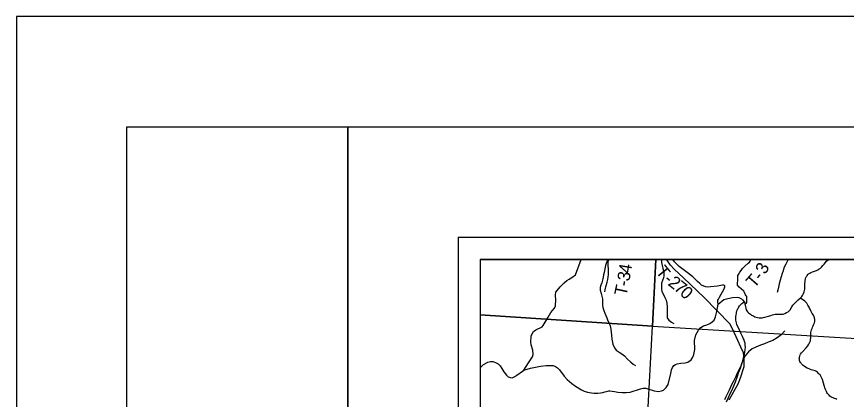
# Model space of a CAD drawing. Extents: x 0 to 34, y 0 to 22.
# Drawn here: x 0 to 3.758, y 20.265 to 22 of the extents above; entities that cross this region are included whole.
import ezdxf

# ---------------------------------------------------------------- set-up
doc = ezdxf.new("R2010")
doc.units = 0
for name, color, linetype in [('GM_X_Corporation', 7, 'Continuous'), ('GM_X_County_Road', 7, 'Continuous'), ('GM_X_Minor_River', 7, 'Continuous'), ('GM_X_Rail_Line', 7, 'Continuous'), ('GM_X_Township_Road', 7, 'Continuous'), ('GM_X_Township_Road_Text', 7, 'Continuous'), ('SH_Border', 7, 'Continuous'), ('SH_Data', 7, 'Continuous')]:
    doc.layers.add(name, color=color, linetype=linetype)

msp = doc.modelspace()

# ---------------------------------------------------------------- linework, layer by layer
at = {"layer": 'GM_X_Corporation'}
for points in [[(3.3441, 14.1), (8.9, 14.1), (8.9, 20.9), (2.1, 20.9), (2.1, 16.1353), (2.1457, 16.065), (2.3447, 15.6926), (2.4297, 15.5215), (2.465, 15.4504), (2.4884, 15.4033), (2.5769, 15.2135), (2.7849, 14.8403), (2.8931, 14.6544), (3.0297, 14.4867), (3.1386, 14.3654), (3.228, 14.2415)], [(2.8947, 20.9), (2.1, 20.9), (2.1, 20.6488), (2.8805, 20.5967)], [(6.9348, 20.9), (2.1, 20.9), (2.1, 19.6396), (2.105, 19.6393), (2.5886, 19.6074), (3.0215, 19.5789), (3.8201, 19.5262), (3.8692, 19.5228), (4.8375, 19.4557), (5.0201, 19.4401), (5.6539, 19.3859), (5.9419, 19.3649), (6.5423, 19.3229), (6.824, 19.3005), (6.835, 19.4037), (6.8961, 20.3303), (6.9032, 20.4198)], [(3.9048, 20.9), (2.8947, 20.9), (2.8805, 20.5967), (3.8795, 20.5363)], [(2.1, 20.6488), (2.1, 19.629), (2.8266, 19.5815), (2.8805, 20.5967)], [(3.8795, 20.5363), (3.8179, 19.5177), (2.8266, 19.5815), (2.8805, 20.5967)]]:
    msp.add_lwpolyline(points, close=True, dxfattribs=at)
at = {"layer": 'GM_X_County_Road'}
msp.add_lwpolyline([(3.7158, 20.265), (3.7107, 20.2674), (3.7051, 20.2693), (3.6992, 20.272), (3.6943, 20.2742), (3.6887, 20.2772), (3.6841, 20.2804), (3.6803, 20.2839), (3.6763, 20.2884), (3.6735, 20.2919), (3.6705, 20.2969), (3.6677, 20.3016), (3.665, 20.3078), (3.6629, 20.3132), (3.6578, 20.3283), (3.6547, 20.339), (3.6495, 20.3559), (3.6462, 20.364), (3.6429, 20.3701), (3.6393, 20.376), (3.6358, 20.3804), (3.6312, 20.3848), (3.6271, 20.3882), (3.6223, 20.3914), (3.6167, 20.3942), (3.6106, 20.3963), (3.6049, 20.3977), (3.5993, 20.3995), (3.5931, 20.4022), (3.5855, 20.4052), (3.5807, 20.4075), (3.5736, 20.4112), (3.5675, 20.4153), (3.5627, 20.419), (3.5586, 20.4228), (3.5551, 20.4262), (3.5531, 20.429), (3.5501, 20.4331), (3.5482, 20.437), (3.5463, 20.4421), (3.5455, 20.4467), (3.5451, 20.4509), (3.5455, 20.4543), (3.5462, 20.458), (3.5472, 20.462), (3.5489, 20.4666), (3.5513, 20.4707), (3.5547, 20.4759), (3.5589, 20.4808), (3.5761, 20.4991), (3.5833, 20.5078), (3.5883, 20.5158), (3.5918, 20.5216), (3.594, 20.5273), (3.5953, 20.5313), (3.5961, 20.5348), (3.5966, 20.5391), (3.597, 20.5434), (3.5971, 20.5512), (3.597, 20.5554), (3.5972, 20.5588), (3.5975, 20.5638), (3.5979, 20.5685), (3.5993, 20.5746), (3.6006, 20.5804), (3.603, 20.5871), (3.605, 20.5922), (3.6079, 20.5987), (3.6098, 20.6034), (3.6122, 20.6097), (3.6133, 20.613), (3.6148, 20.6182), (3.6151, 20.6219), (3.6152, 20.6258), (3.615, 20.6291), (3.6145, 20.6321), (3.6137, 20.6357), (3.6119, 20.6398), (3.6088, 20.6466), (3.6041, 20.6547), (3.5973, 20.6674), (3.5951, 20.6715), (3.5918, 20.6783), (3.5891, 20.683), (3.5865, 20.6885), (3.5844, 20.6925), (3.5829, 20.6953), (3.5792, 20.7007), (3.5745, 20.7061), (3.5696, 20.7103), (3.5554, 20.721), (3.5493, 20.724)], dxfattribs=at)
at = {"layer": 'GM_X_Minor_River'}
for points in [[(2.6767, 20.9), (2.676, 20.8983), (2.6673, 20.8721), (2.6643, 20.8577), (2.6609, 20.841), (2.6579, 20.8293), (2.6567, 20.8186), (2.6541, 20.805), (2.6503, 20.794), (2.6469, 20.7834), (2.6439, 20.7731), (2.6427, 20.761), (2.6473, 20.7447), (2.654, 20.7204), (2.6533, 20.7045), (2.6533, 20.692), (2.6548, 20.6813), (2.6605, 20.6684), (2.665, 20.6556), (2.6695, 20.6449), (2.6733, 20.6347), (2.6782, 20.6211), (2.6839, 20.6101), (2.688, 20.5994), (2.6918, 20.5831), (2.6937, 20.5699), (2.6948, 20.5562), (2.6967, 20.5376), (2.7013, 20.516), (2.7081, 20.4997), (2.7164, 20.4891), (2.7292, 20.4792), (2.7417, 20.4724), (2.753, 20.4622), (2.7674, 20.4474), (2.7799, 20.436), (2.7927, 20.4254), (2.8033, 20.4197)], [(2.9209, 20.9), (2.9206, 20.8969), (2.9217, 20.8852), (2.9244, 20.8719), (2.927, 20.859), (2.9293, 20.8492), (2.9308, 20.8382), (2.9312, 20.826), (2.9293, 20.8162), (2.9259, 20.8048), (2.9217, 20.7919), (2.9206, 20.7771), (2.9209, 20.7646), (2.9228, 20.7543), (2.9293, 20.7411), (2.9364, 20.7274), (2.9425, 20.7145), (2.9455, 20.7013), (2.9466, 20.6853), (2.947, 20.6713), (2.9466, 20.6599), (2.9462, 20.647), (2.9474, 20.6349), (2.9549, 20.6243), (2.967, 20.6156), (2.9768, 20.6099)], [(3.4935, 20.9), (3.491, 20.8927), (3.4842, 20.8787), (3.4751, 20.8612), (3.4717, 20.848), (3.4668, 20.8358), (3.463, 20.821), (3.4585, 20.8051), (3.4543, 20.7892), (3.4509, 20.7736), (3.4475, 20.7607), (3.4449, 20.7505)], [(3.4802, 20.5768), (3.4623, 20.5586), (3.4449, 20.5445), (3.4256, 20.532), (3.4047, 20.5244), (3.3873, 20.5179), (3.3687, 20.5107), (3.3486, 20.5024), (3.3316, 20.494), (3.3145, 20.4815), (3.3001, 20.4629), (3.291, 20.4446), (3.2826, 20.426), (3.2776, 20.4059), (3.2681, 20.3838), (3.262, 20.3648), (3.2548, 20.3431), (3.2472, 20.326), (3.2388, 20.307), (3.23, 20.2899), (3.2232, 20.2724), (3.2144, 20.2527)]]:
    msp.add_lwpolyline(points, dxfattribs=at)
at = {"layer": 'GM_X_Rail_Line'}
msp.add_lwpolyline([(3.2278, 20.2639), (3.2688, 20.3363), (3.2793, 20.3637), (3.2956, 20.4152), (3.2956, 20.4492), (3.2926, 20.4765), (3.2806, 20.5024), (3.2672, 20.5318), (3.2431, 20.5858), (3.2302, 20.6083), (3.1144, 20.7274), (3.0211, 20.8167), (2.978, 20.8554), (2.9619, 20.8739), (2.945, 20.8977), (2.9437, 20.9)], dxfattribs=at)
at = {"layer": 'GM_X_Township_Road'}
for points in [[(2.1, 20.4087), (2.1001, 20.4088), (2.1149, 20.4228), (2.1347, 20.4338), (2.1464, 20.4368), (2.1563, 20.4368), (2.1696, 20.4333), (2.1808, 20.4266), (2.1897, 20.4177), (2.1978, 20.4048), (2.2067, 20.39), (2.2187, 20.3755), (2.2266, 20.3676), (2.2357, 20.3643), (2.2441, 20.3638), (2.2561, 20.3689), (2.2659, 20.3754), (2.2909, 20.3931), (2.2979, 20.3977), (2.3271, 20.4067), (2.3725, 20.4157), (2.3983, 20.419), (2.419, 20.419), (2.4296, 20.4187), (2.4413, 20.4143), (2.45, 20.4089), (2.4595, 20.399), (2.4797, 20.3712), (2.4938, 20.3554), (2.515, 20.338), (2.5314, 20.326), (2.5586, 20.3081), (2.5703, 20.3024), (2.5859, 20.2987), (2.6035, 20.2947), (2.6139, 20.2934), (2.632, 20.293), (2.6447, 20.2946), (2.6551, 20.2974), (2.664, 20.3002), (2.6725, 20.3019), (2.682, 20.3035), (2.6874, 20.3037), (2.7079, 20.3009), (2.7227, 20.2983), (2.7435, 20.2964), (2.7611, 20.297), (2.7796, 20.2986), (2.8265, 20.3135), (2.8374, 20.3162), (2.8496, 20.316), (2.8873, 20.3045), (2.9074, 20.3016), (2.9207, 20.3037), (2.9297, 20.307), (2.9424, 20.3195), (2.9517, 20.3336), (2.9632, 20.3825), (2.9661, 20.4001), (2.9703, 20.4095), (2.9776, 20.4189), (2.9841, 20.4231), (2.9916, 20.4264), (3.0081, 20.4295), (3.0282, 20.4304), (3.0397, 20.4344), (3.055, 20.4448), (3.0627, 20.4563), (3.0667, 20.4693), (3.0715, 20.4913), (3.0702, 20.5323), (3.0769, 20.5587), (3.0891, 20.5796), (3.0995, 20.5909), (3.1112, 20.5984), (3.126, 20.603), (3.1405, 20.609), (3.1507, 20.6162), (3.1589, 20.6239), (3.1649, 20.6388), (3.1712, 20.6635), (3.1784, 20.6968), (3.2038, 20.718), (3.2212, 20.7224), (3.2431, 20.7268), (3.264, 20.7291), (3.2711, 20.7274), (3.2828, 20.7205), (3.288, 20.7164), (3.2958, 20.7076), (3.2981, 20.7025), (3.2989, 20.6978), (3.301, 20.6855), (3.3026, 20.6784), (3.3045, 20.6714), (3.3069, 20.6668), (3.3102, 20.662), (3.3145, 20.6578), (3.3189, 20.6543), (3.3238, 20.651), (3.3291, 20.6478), (3.3332, 20.6456), (3.3395, 20.6422), (3.3436, 20.64), (3.3561, 20.6367), (3.3635, 20.6355), (3.3713, 20.635), (3.3767, 20.6353), (3.3814, 20.6359), (3.3897, 20.6383), (3.3993, 20.6413), (3.4168, 20.6463), (3.4231, 20.6482), (3.4301, 20.6501), (3.4351, 20.6509), (3.4398, 20.6513), (3.452, 20.6511), (3.4642, 20.6511), (3.472, 20.6523), (3.4801, 20.6549), (3.4879, 20.6584), (3.4945, 20.6619), (3.4982, 20.6653), (3.5031, 20.671), (3.5117, 20.6847), (3.5161, 20.6919), (3.523, 20.6998), (3.5272, 20.7045), (3.5339, 20.7109), (3.5405, 20.7169), (3.5493, 20.724), (3.5571, 20.7315), (3.5601, 20.7366), (3.5649, 20.7458), (3.5671, 20.7524), (3.5687, 20.7592), (3.5695, 20.7643), (3.57, 20.7713), (3.5701, 20.7795), (3.5703, 20.7906), (3.571, 20.7981), (3.5721, 20.804), (3.5734, 20.8115), (3.575, 20.817), (3.5767, 20.8215), (3.5787, 20.8245), (3.5808, 20.8275), (3.5833, 20.8308), (3.5872, 20.8339), (3.5933, 20.8377), (3.5978, 20.84), (3.6056, 20.843), (3.6225, 20.8495), (3.6289, 20.8529), (3.6331, 20.8551), (3.6357, 20.8568), (3.6406, 20.8607), (3.6455, 20.8651), (3.6522, 20.8725), (3.6575, 20.8784), (3.6688, 20.8912), (3.6769, 20.9)], [(2.2979, 20.3977), (2.3189, 20.4315), (2.3371, 20.4586), (2.34, 20.4691), (2.3378, 20.4882), (2.3302, 20.512), (2.3295, 20.525), (2.3313, 20.5524), (2.3356, 20.5632), (2.3414, 20.5733), (2.3522, 20.5813), (2.3799, 20.5949), (2.3851, 20.5996), (2.3899, 20.6074), (2.4074, 20.6386), (2.4193, 20.6595), (2.4351, 20.6775), (2.4406, 20.688), (2.4416, 20.6959), (2.4417, 20.7119), (2.4405, 20.7398), (2.4431, 20.7507), (2.4482, 20.7595), (2.4616, 20.7758), (2.4799, 20.7934), (2.4919, 20.8043), (2.5027, 20.8106), (2.5152, 20.818), (2.5308, 20.8299), (2.5574, 20.9)], [(2.6648, 20.7526), (2.6659, 20.762), (2.6678, 20.7701), (2.6689, 20.776), (2.6751, 20.7967), (2.6779, 20.8092), (2.68, 20.8211), (2.6802, 20.8298), (2.6808, 20.8535), (2.6793, 20.873), (2.6789, 20.8865), (2.6798, 20.8919), (2.6817, 20.8967), (2.6835, 20.9)], [(3.1784, 20.6968), (3.1755, 20.7072), (3.1764, 20.7145), (3.1785, 20.7191), (3.1842, 20.7287), (3.2046, 20.7667), (3.2083, 20.7755), (3.2082, 20.7793), (3.2058, 20.7819), (3.2028, 20.7831), (3.1966, 20.7833), (3.1746, 20.7779), (3.143, 20.7747), (3.1281, 20.7744), (3.1215, 20.7756), (3.1123, 20.778), (3.1027, 20.7835), (3.0947, 20.7898), (3.0842, 20.7998), (3.0627, 20.8202), (3.0373, 20.8407), (3.0017, 20.868), (2.98, 20.8882), (2.9723, 20.9)], [(3.2989, 20.6978), (3.3029, 20.6994), (3.3061, 20.7018), (3.3072, 20.7039), (3.3081, 20.7104), (3.3081, 20.7155), (3.3072, 20.7208), (3.3075, 20.7262), (3.3068, 20.7313), (3.3052, 20.7346), (3.3016, 20.7388), (3.297, 20.7497), (3.2937, 20.7564), (3.2732, 20.7735), (3.2657, 20.7832), (3.2653, 20.7863), (3.2658, 20.7942), (3.2661, 20.8033), (3.2662, 20.8137), (3.2669, 20.8211), (3.2674, 20.8265), (3.269, 20.8311), (3.2752, 20.8419), (3.2814, 20.8501), (3.2885, 20.8589), (3.299, 20.8688), (3.3137, 20.882), (3.3189, 20.8879), (3.3221, 20.8924), (3.3245, 20.8966), (3.3259, 20.9)], [(3.2074, 20.2649), (3.2134, 20.2779), (3.2286, 20.3091), (3.2414, 20.3353), (3.2469, 20.3468), (3.2586, 20.3711), (3.2659, 20.3859), (3.2734, 20.4012), (3.2827, 20.4219), (3.2877, 20.4357), (3.293, 20.4544), (3.2951, 20.4627), (3.2967, 20.47), (3.2989, 20.4793), (3.3001, 20.4917), (3.3009, 20.5011), (3.3003, 20.5116), (3.2992, 20.5208), (3.2972, 20.5281), (3.2948, 20.5347), (3.293, 20.5393), (3.2877, 20.5507), (3.2808, 20.566), (3.2738, 20.5798), (3.2696, 20.5892), (3.2629, 20.6036), (3.2601, 20.6119), (3.2585, 20.6187), (3.2578, 20.6246), (3.2574, 20.6304), (3.2573, 20.6344), (3.2578, 20.6403), (3.2593, 20.6492), (3.2601, 20.6553), (3.261, 20.6598), (3.2628, 20.6671), (3.265, 20.6729), (3.2674, 20.6775), (3.2693, 20.6808), (3.2715, 20.6851), (3.2742, 20.6889), (3.2762, 20.6916), (3.2813, 20.6972), (3.2852, 20.7005), (3.2887, 20.703), (3.2958, 20.7076)]]:
    msp.add_lwpolyline(points, dxfattribs=at)
at = {"layer": 'SH_Border'}
for points in [[(0.5, 21.5), (1.5, 21.5), (1.5, 0.5), (0.5, 0.5)], [(1.5, 21.5), (33.5, 21.5), (33.5, 0.5), (1.5, 0.5)]]:
    msp.add_lwpolyline(points, close=True, dxfattribs=at)
at = {"layer": 'SH_Data'}
for p, q in [((2, 21), (9, 21)), ((2, 21), (2, 14)), ((2.1, 20.9), (2.1, 14.1)), ((2.1, 20.9), (8.9, 20.9))]:
    msp.add_line(p, q, dxfattribs=at)
msp.add_lwpolyline([(0, 0), (34, 0), (34, 22), (0, 22)], close=True, dxfattribs=at)

# ---------------------------------------------------------------- texts
at = {"layer": 'GM_X_Township_Road_Text'}
for s, rotation, p in [('4', 80.8357, (2.7816, 20.8334)), ('T', 309.2829, (2.8921, 20.843)), ('3', 62.8739, (3.3926, 20.829)), ('3', 80.115, (2.7754, 20.7981)), ('2', 321.8, (2.9467, 20.7858)), ('T', 48.938, (3.3414, 20.7666)), ('-', 50.337, (3.3703, 20.7998)), ('T', 77.7924, (2.7616, 20.7312)), ('-', 79.3361, (2.771, 20.7743)), ('-', 320.4799, (2.9276, 20.8015)), ('7', 320.9607, (2.974, 20.7643)), ('0', 317.1494, (3.0004, 20.7429))]:
    msp.add_text(s, height=0.0568, rotation=rotation, dxfattribs=at).set_placement(p)

doc.saveas('drawing.dxf')
